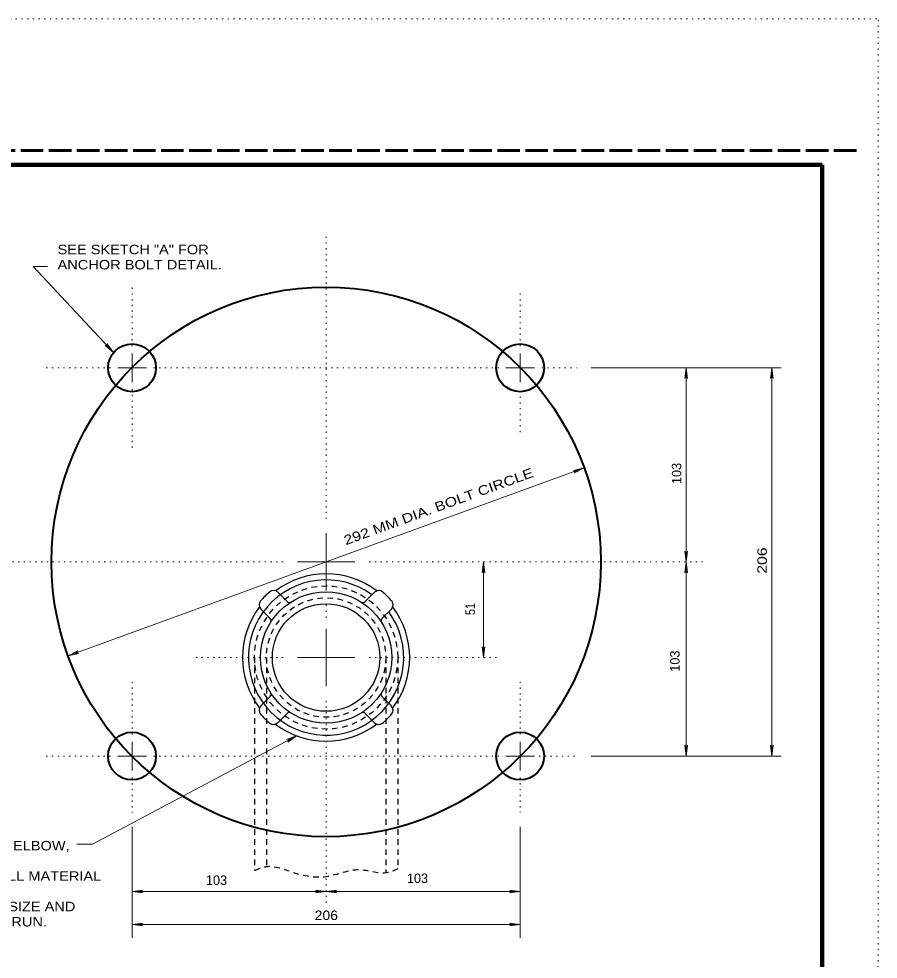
# Model space of a CAD drawing. Extents: x 312583 to 312854, y 144419 to 144597.
# Drawn here: x 312784.5 to 312853.5, y 144521.4 to 144596.8 of the extents above; entities that cross this region are included whole.
import ezdxf

# ---------------------------------------------------------------- set-up
doc = ezdxf.new("R2010")
doc.units = 0
doc.header["$LTSCALE"] = 0.3
for name, pattern in [('DOTTED', [1.5, 0.3, -1.2]), ('LONG_DASHED', [7.5, 6, -1.5]), ('SHORT_DASHED', [2.7, 1.5, -1.2])]:
    doc.linetypes.add(name, pattern=pattern)
for name, color, linetype, lineweight in [('1', 7, 'Continuous', 25), ('2', 7, 'Continuous', 13), ('62', 7, 'DOTTED', 13), ('63', 7, 'LONG_DASHED', 60)]:
    doc.layers.add(name, color=color, linetype=linetype, lineweight=lineweight)

msp = doc.modelspace()

# ---------------------------------------------------------------- linework, layer by layer
at = {"layer": '1', "lineweight": 158}
msp.add_line((312849, 144423.1446), (312849, 144585.0846), dxfattribs=at)
at = {"layer": '1'}
for p, q in [((312806.0698, 144550.0362), (312805.3108, 144550.7952)), ((312812.3181, 144550.0362), (312813.0771, 144550.7952)), ((312804.7128, 144548.6792), (312803.9538, 144549.4382)), ((312813.6751, 144548.6792), (312814.4341, 144549.4382)), ((312804.7128, 144542.4309), (312803.9538, 144541.6719)), ((312813.6751, 144542.4309), (312814.4341, 144541.6719)), ((312806.0698, 144541.0739), (312805.3108, 144540.3149)), ((312812.3181, 144541.0739), (312813.0771, 144540.3149))]:
    msp.add_line(p, q, dxfattribs=at)
at = {"layer": '1', "linetype": 'SHORT_DASHED'}
for p, q in [((312803.4478, 144545.5512), (312803.4478, 144528.4546)), ((312804.4061, 144545.5512), (312804.4061, 144528.7612)), ((312813.9894, 144545.5512), (312813.9894, 144528.2782)), ((312814.9478, 144545.5512), (312814.9478, 144528.6002))]:
    msp.add_line(p, q, dxfattribs=at)
at = {"layer": '1', "lineweight": 158}
msp.add_lwpolyline([(312616.5, 144423.1446), (312616.5, 144585.0846), (312849, 144585.0846)], dxfattribs=at)
at = {"layer": '1', "lineweight": 40}
for centre, radius in [((312809.1939, 144553.2179), 22.0417), ((312793.6191, 144568.7927), 1.9167), ((312824.7649, 144568.7927), 1.9167), ((312793.6191, 144537.6469), 1.9167), ((312824.7649, 144537.6469), 1.9167)]:
    msp.add_circle(centre, radius, dxfattribs=at)
at = {"layer": '1', "linetype": 'SHORT_DASHED'}
for radius in [5.75, 4.7917]:
    msp.add_circle((312809.1939, 144545.5512), radius, dxfattribs=at)
at = {"layer": '1'}
for radius in [5.2708, 4.3125]:
    msp.add_circle((312809.1939, 144545.5512), radius, dxfattribs=at)
for centre, radius, start, end in [((312809.1939, 144545.5512), 6.2292, 53.86372, 36.13885), ((312809.1939, 144545.5512), 6.7083, 52.73077, 127.13133), ((312809.1939, 144545.5512), 6.9479, 130.45728, 139.11748), ((312804.9721, 144550.4524), 0.4792, 45, 130.74122), ((312813.4284, 144550.4421), 0.4792, 49.10641, 135), ((312804.3031, 144549.7857), 0.4792, 139.10641, 225), ((312809.1939, 144545.5512), 6.9479, 40.45728, 49.11747), ((312814.0951, 144549.773), 0.4792, 315, 40.74122), ((312809.1939, 144545.5512), 6.7083, 142.73077, 217.13133), ((312806.2388, 144550.2022), 0.2396, 225, 302.43125), ((312812.1491, 144550.2022), 0.2396, 237.56875, 315), ((312809.1939, 144545.5512), 6.7083, 322.73077, 37.13133), ((312804.5429, 144548.5064), 0.2396, 327.56875, 45), ((312813.8449, 144548.5064), 0.2396, 135, 212.43125), ((312804.5429, 144542.5961), 0.2396, 315, 32.43125), ((312813.8449, 144542.5961), 0.2396, 147.56875, 225), ((312804.2928, 144541.3294), 0.4792, 135, 220.74122), ((312809.1939, 144545.5512), 6.9479, 220.45728, 229.11748), ((312806.2388, 144540.9002), 0.2396, 57.56875, 135), ((312812.1491, 144540.9002), 0.2396, 45, 122.43125), ((312814.0848, 144541.3167), 0.4792, 319.10641, 45), ((312804.9594, 144540.6604), 0.4792, 229.10641, 315), ((312813.4157, 144540.6501), 0.4792, 225, 310.74122), ((312809.1939, 144545.5512), 6.9479, 310.45727, 319.11747), ((312809.1939, 144545.5512), 6.7083, 232.73077, 307.13133)]:
    msp.add_arc(centre, radius, start, end, dxfattribs=at)
at = {"layer": '1', "linetype": 'SHORT_DASHED'}
msp.add_spline([(312814.9478, 144528.6002), (312813.9894, 144528.2782), (312811.8811, 144528.5159), (312809.1978, 144527.9639), (312806.5144, 144528.3089), (312804.4061, 144528.7612), (312803.4478, 144528.4546)], degree=3, dxfattribs=at)
at = {"layer": '2', "linetype": 'DOTTED'}
for p, q in [((312809.1978, 144556.6679), (312809.1978, 144579.6679)), ((312793.6191, 144570.5216), (312793.6191, 144575.5279)), ((312824.7688, 144570.5216), (312824.7688, 144574.8149)), ((312791.8941, 144568.7966), (312786.3971, 144568.7966)), ((312795.3441, 144568.7966), (312823.0438, 144568.7966)), ((312826.4938, 144568.7966), (312829.2844, 144568.7966)), ((312793.6191, 144567.0716), (312793.6191, 144562.0576)), ((312824.7688, 144563.6216), (312824.7688, 144567.0716)), ((312805.7478, 144553.2179), (312782.7478, 144553.2179)), ((312812.6478, 144553.2179), (312839.4121, 144553.2179)), ((312809.1978, 144549.7679), (312809.1978, 144548.6486)), ((312805.7478, 144545.5512), (312798.6331, 144545.5512)), ((312812.6478, 144545.5512), (312823.0361, 144545.5512)), ((312793.6191, 144539.3719), (312793.6191, 144543.6652)), ((312824.7688, 144539.3719), (312824.7688, 144543.6652)), ((312809.1978, 144542.0782), (312809.1978, 144525.7412)), ((312791.8941, 144537.6469), (312786.3971, 144537.6469)), ((312795.3441, 144537.6469), (312823.0438, 144537.6469)), ((312826.2868, 144537.6469), (312829.2844, 144537.6469)), ((312793.6191, 144535.9219), (312793.6191, 144533.1236)), ((312824.7688, 144535.9219), (312824.7688, 144533.1236))]:
    msp.add_line(p, q, dxfattribs=at)
at = {"layer": '2'}
for p, q in [((312785.6841, 144576.9232), (312786.8303, 144576.9232)), ((312792.1318, 144570.0079), (312785.6841, 144576.9232)), ((312791.4648, 144570.5676), (312791.7331, 144570.4372)), ((312792.1318, 144570.0079), (312791.4648, 144570.5676)), ((312791.6181, 144570.7132), (312791.7331, 144570.4372)), ((312792.1318, 144570.0079), (312791.6181, 144570.7132)), ((312793.6191, 144568.7966), (312793.6191, 144569.9466)), ((312824.7688, 144568.7966), (312824.7688, 144569.9466)), ((312793.6191, 144568.7966), (312792.4691, 144568.7966)), ((312793.6191, 144568.7966), (312794.7691, 144568.7966)), ((312793.6191, 144568.7966), (312793.6191, 144567.6466)), ((312824.7688, 144568.7966), (312823.6188, 144568.7966)), ((312824.7688, 144568.7966), (312825.9188, 144568.7966)), ((312824.7688, 144568.7966), (312824.7688, 144567.6466)), ((312830.4574, 144568.7966), (312845.7064, 144568.7966)), ((312838.1011, 144568.7966), (312837.9938, 144567.9302)), ((312837.9938, 144567.9302), (312838.1011, 144568.2062)), ((312838.1011, 144568.7966), (312838.2084, 144567.9302)), ((312838.2084, 144567.9302), (312838.1011, 144568.2062)), ((312844.9628, 144568.7966), (312844.8554, 144567.9302)), ((312844.8554, 144567.9302), (312844.9628, 144568.2062)), ((312844.9628, 144568.7966), (312845.0701, 144567.9302)), ((312844.9628, 144537.6469), (312844.9628, 144568.7966)), ((312845.0701, 144567.9302), (312844.9628, 144568.2062)), ((312788.4824, 144545.6816), (312829.9054, 144560.7619)), ((312829.9054, 144560.7619), (312829.0544, 144560.5626)), ((312829.9054, 144560.7619), (312829.1311, 144560.3632)), ((312829.0544, 144560.5626), (312829.3534, 144560.5549)), ((312829.1311, 144560.3632), (312829.3534, 144560.5549)), ((312809.1978, 144553.2179), (312809.1978, 144555.5179)), ((312837.9938, 144554.0842), (312838.1011, 144553.8082)), ((312838.1011, 144553.2179), (312837.9938, 144554.0842)), ((312838.2084, 144554.0842), (312838.1011, 144553.8082)), ((312838.1011, 144553.2179), (312838.2084, 144554.0842)), ((312809.1978, 144553.2179), (312806.8978, 144553.2179)), ((312809.1978, 144553.2179), (312811.4978, 144553.2179)), ((312809.1978, 144553.2179), (312809.1978, 144550.9179)), ((312821.8171, 144553.2179), (312821.7098, 144552.3516)), ((312821.8171, 144545.5512), (312821.8171, 144553.2179)), ((312821.8171, 144553.2179), (312821.9244, 144552.3516)), ((312838.1011, 144553.2179), (312837.9938, 144552.3516)), ((312838.1011, 144553.2179), (312838.2084, 144552.3516)), ((312821.7098, 144552.3516), (312821.8171, 144552.6276)), ((312821.9244, 144552.3516), (312821.8171, 144552.6276)), ((312837.9938, 144552.3516), (312838.1011, 144552.6276)), ((312838.2084, 144552.3516), (312838.1011, 144552.6276)), ((312809.1978, 144545.5512), (312809.1978, 144547.8512)), ((312821.7098, 144546.4176), (312821.8171, 144546.1416)), ((312821.8171, 144545.5512), (312821.7098, 144546.4176)), ((312821.9244, 144546.4176), (312821.8171, 144546.1416)), ((312821.8171, 144545.5512), (312821.9244, 144546.4176)), ((312788.4824, 144545.6816), (312789.2644, 144546.0802)), ((312788.4824, 144545.6816), (312789.3334, 144545.8732)), ((312789.2644, 144546.0802), (312789.0421, 144545.8809)), ((312789.3334, 144545.8732), (312789.0421, 144545.8809)), ((312809.1978, 144545.5512), (312806.8978, 144545.5512)), ((312809.1978, 144545.5512), (312811.4978, 144545.5512)), ((312809.1978, 144545.5512), (312809.1978, 144543.2512)), ((312806.8288, 144539.2722), (312790.4374, 144530.5706)), ((312793.6191, 144537.6469), (312793.6191, 144538.7969)), ((312806.8288, 144539.2722), (312806.0161, 144538.9656)), ((312806.0161, 144538.9656), (312806.3074, 144538.9962)), ((312806.8288, 144539.2722), (312806.1158, 144538.7739)), ((312806.1158, 144538.7739), (312806.3074, 144538.9962)), ((312824.7688, 144537.6469), (312824.7688, 144538.7969)), ((312837.9938, 144538.5132), (312838.1011, 144538.2372)), ((312838.1011, 144537.6469), (312837.9938, 144538.5132)), ((312838.2084, 144538.5132), (312838.1011, 144538.2372)), ((312838.1011, 144537.6469), (312838.2084, 144538.5132)), ((312844.8554, 144538.5132), (312844.9628, 144538.2372)), ((312844.9628, 144537.6469), (312844.8554, 144538.5132)), ((312845.0701, 144538.5132), (312844.9628, 144538.2372)), ((312844.9628, 144537.6469), (312845.0701, 144538.5132)), ((312793.6191, 144537.6469), (312792.4691, 144537.6469)), ((312793.6191, 144537.6469), (312794.7691, 144537.6469)), ((312793.6191, 144537.6469), (312793.6191, 144536.4969)), ((312824.7688, 144537.6469), (312823.6188, 144537.6469)), ((312824.7688, 144537.6469), (312825.9188, 144537.6469)), ((312824.7688, 144537.6469), (312824.7688, 144536.4969)), ((312830.4574, 144537.6469), (312845.7064, 144537.6469)), ((312793.6268, 144531.9582), (312793.6268, 144523.076)), ((312824.7688, 144531.9582), (312824.7688, 144523.076)), ((312789.198, 144530.5706), (312790.4374, 144530.5706)), ((312793.6268, 144526.7929), (312794.4931, 144526.9002)), ((312793.6268, 144526.7929), (312794.4931, 144526.6855)), ((312794.4931, 144526.9002), (312794.2171, 144526.7929)), ((312794.4931, 144526.6855), (312794.2171, 144526.7929)), ((312808.3314, 144526.9002), (312808.6074, 144526.7929)), ((312809.1978, 144526.7929), (312808.3314, 144526.9002)), ((312808.3314, 144526.6855), (312808.6074, 144526.7929)), ((312809.1978, 144526.7929), (312808.3314, 144526.6855)), ((312809.1978, 144526.7929), (312810.0641, 144526.9002)), ((312809.1978, 144526.7929), (312810.0641, 144526.6855)), ((312810.0641, 144526.9002), (312809.7881, 144526.7929)), ((312810.0641, 144526.6855), (312809.7881, 144526.7929)), ((312823.9024, 144526.9002), (312824.1784, 144526.7929)), ((312824.7688, 144526.7929), (312823.9024, 144526.9002)), ((312823.9024, 144526.6855), (312824.1784, 144526.7929)), ((312824.7688, 144526.7929), (312823.9024, 144526.6855)), ((312793.6268, 144524.1274), (312794.4931, 144524.2347)), ((312793.6268, 144524.1274), (312794.4931, 144524.0201)), ((312793.6268, 144524.1274), (312824.7688, 144524.1274)), ((312794.4931, 144524.2347), (312794.2171, 144524.1274)), ((312794.4931, 144524.0201), (312794.2171, 144524.1274)), ((312823.9024, 144524.2347), (312824.1784, 144524.1274)), ((312824.7688, 144524.1274), (312823.9024, 144524.2347)), ((312823.9024, 144524.0201), (312824.1784, 144524.1274)), ((312824.7688, 144524.1274), (312823.9024, 144524.0201))]:
    msp.add_line(p, q, dxfattribs=at)
for points in [[(312838.1011, 144537.6469), (312838.1011, 144553.2179), (312838.1011, 144568.7966)], [(312793.6268, 144526.7929), (312809.1978, 144526.7929), (312824.7688, 144526.7929)]]:
    msp.add_lwpolyline(points, dxfattribs=at)
at = {"layer": '62'}
msp.add_line((312601.2, 144596.7846), (312853.5, 144596.7846), dxfattribs=at)
msp.add_lwpolyline([(312601.2, 144418.5846), (312853.5, 144418.5846), (312853.5, 144596.7846)], dxfattribs=at)
at = {"layer": '63'}
msp.add_line((312851.75, 144586.2246), (312583.526, 144586.2246), dxfattribs=at)

# ---------------------------------------------------------------- texts
at = {"layer": '2'}
for s, width, p in [('SEE SKETCH "A" FOR', 1.15, (312787.6448, 144577.9015)), ('ANCHOR BOLT DETAIL.', 1.15, (312787.6448, 144576.6815)), ('RIGID METALLIC CONDUIT,  ELBOW,', 1.15, (312768.1605, 144530.0788)), ('BONDING BUSHING ETC.  ALL MATERIAL', 1.15, (312768.1605, 144527.6388)), ('SEE GENERAL PLANS FOR SIZE AND', 1.15, (312768.1605, 144525.1988)), ('206', 1.1, (312808.2786, 144524.494)), ('DIRECTION CONDUIT IS TO RUN.', 1.15, (312768.1605, 144523.9788))]:
    msp.add_text(s, height=0.76, dxfattribs=dict(at, width=width)).set_placement(p)
for s, rotation, width, p in [('292 MM DIA. BOLT CIRCLE', 20.004, 1.25, (312810.7827, 144554.5599)), ('206 ', 90, 1.25, (312844.5622, 144552.2688)), ('51', 90, 0.85, (312821.1363, 144548.961))]:
    msp.add_text(s, height=0.76, rotation=rotation, dxfattribs=dict(at, width=width)).set_placement(p)
for p in [(312837.7005, 144559.4666), (312837.5604, 144544.4123)]:
    msp.add_text('103', height=0.76, rotation=90, dxfattribs=at).set_placement(p)
for p in [(312815.6802, 144527.4628), (312799.5534, 144527.3124)]:
    msp.add_text('103', height=0.76, dxfattribs=at).set_placement(p)

doc.saveas('drawing.dxf')
